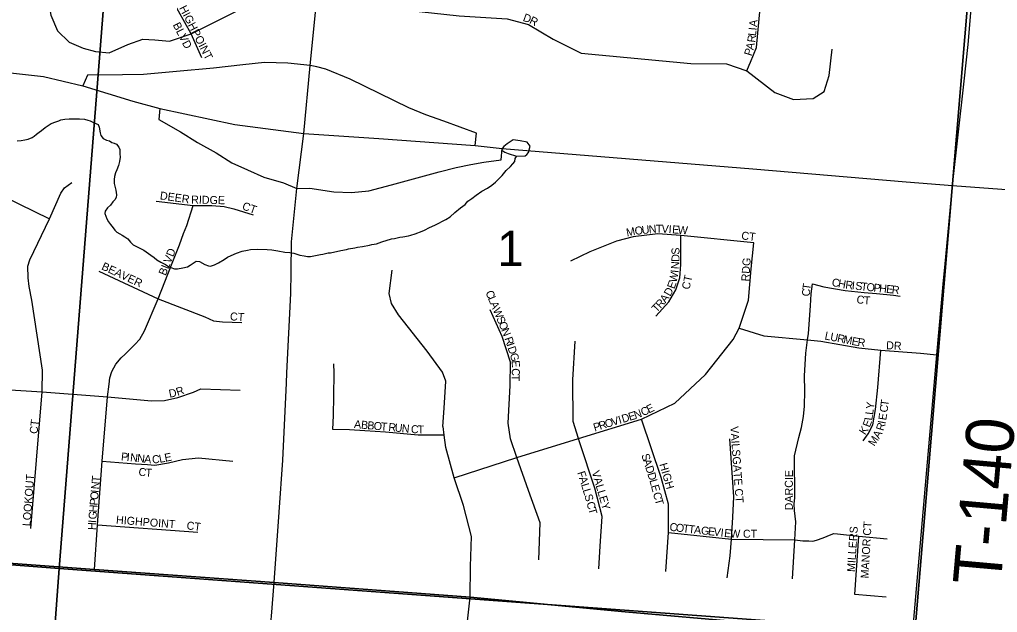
# Model space of a CAD drawing. Extents: x 1310247 to 1552180, y 377264 to 706493.
# Drawn here: x 1414286 to 1420398, y 506121 to 509829 of the extents above; entities that cross this region are included whole.
import ezdxf

# ---------------------------------------------------------------- set-up
doc = ezdxf.new("R2010")
doc.units = 0
for name, color, linetype in [('GM_X_County_Road', 7, 'Continuous'), ('GM_X_Interchange_Ramps', 7, 'Continuous'), ('GM_X_Minor_River', 7, 'Continuous'), ('GM_X_Section', 7, 'Continuous'), ('GM_X_Section_Text', 7, 'Continuous'), ('GM_X_State_Route', 7, 'Continuous'), ('GM_X_Township', 7, 'Continuous'), ('GM_X_Township_Road', 7, 'Continuous'), ('GM_X_Township_Road_Text', 7, 'Continuous'), ('GM_X_Township_Subdivision', 7, 'Continuous'), ('GM_X_Township_Subdivision_Text', 7, 'Continuous')]:
    doc.layers.add(name, color=color, linetype=linetype)

msp = doc.modelspace()

# ---------------------------------------------------------------- linework, layer by layer
at = {"layer": 'GM_X_County_Road'}
msp.add_lwpolyline([(1408861.5, 506921.2), (1408897.3, 506907.8), (1408977.9, 506871.8), (1409040.8, 506847.4), (1409093.1, 506831.5), (1409129.4, 506820.4), (1409220, 506815.1), (1409938.6, 506761), (1410365.3, 506728.9), (1410785.2, 506697.3), (1412080.1, 506594.4), (1412114.6, 506591.5), (1412570.9, 506553.7), (1413550.1, 506484), (1414754.7, 506390.5), (1415877.6, 506308.5)], dxfattribs=at)
at = {"layer": 'GM_X_Interchange_Ramps'}
for points in [[(1416101.7, 509542.3), (1415963.9, 509555.5), (1415817.9, 509560.2), (1415681.2, 509546.3), (1415498.2, 509525.4), (1415266.5, 509504.6), (1415060.3, 509486), (1414930.5, 509483.7), (1414710.4, 509481.4), (1414682.6, 509414.2)], [(1417134, 509041.2), (1417143.2, 509117.6), (1416937.3, 509194.5), (1416825.5, 509234.2), (1416719.1, 509277.5), (1416353, 509456.1), (1416201.1, 509518.8), (1416144.6, 509533.6), (1416101.7, 509542.3)], [(1415162.2, 509272.9), (1415157.6, 509203.3), (1415292, 509126.9), (1415398.6, 509059.7), (1415514.4, 508994.8), (1415614, 508932.3), (1415711.3, 508888.3), (1415813.3, 508844.2), (1415936.3, 508807.2), (1416019.8, 508772.6)], [(1416019.8, 508772.6), (1416100.6, 508774.7), (1416251.2, 508751.5), (1416360.1, 508746.9), (1416469, 508758.5), (1416610.3, 508795.6), (1416909.2, 508876.7), (1417015.8, 508904.5), (1417106.2, 508923), (1417187.3, 508936.9), (1417296.1, 508950.8), (1417303.1, 509022.6)]]:
    msp.add_lwpolyline(points, dxfattribs=at)
at = {"layer": 'GM_X_Minor_River'}
for points in [[(1414270.9, 509070.1), (1414297.2, 509073.2), (1414319.4, 509076.4), (1414339.7, 509081.6), (1414364.2, 509090.8), (1414378.6, 509100.3), (1414393.1, 509111.8), (1414409.7, 509125.3), (1414424.1, 509134.8), (1414447, 509154.1), (1414484.1, 509178.8), (1414512.6, 509189.8), (1414530.9, 509195.2), (1414545.3, 509202.7), (1414569.5, 509205.8), (1414595.8, 509208.9), (1414617.9, 509208), (1414646, 509209), (1414660.1, 509208.5), (1414692.2, 509205.3), (1414714.1, 509200.5), (1414728, 509195.9), (1414751.7, 509183), (1414777.4, 509172), (1414784.8, 509155.7), (1414789.6, 509121.3), (1414794.9, 509103), (1414808.3, 509084.4), (1414830.1, 509075.6), (1414848, 509070.9), (1414863.7, 509060.3), (1414877.6, 509055.8), (1414891.5, 509049.2), (1414906.9, 509030.6), (1414912.4, 509016.3), (1414913.4, 508990.1), (1414914.6, 508968), (1414911.6, 508941.9), (1414904.7, 508916.1), (1414893.6, 508888.3), (1414886.9, 508870.5), (1414880, 508846.6), (1414877.3, 508828.6), (1414878.4, 508804.5)], [(1417392.5, 508974.2), (1417446.4, 508975.9), (1417456.7, 508985.7), (1417467.1, 508997.4), (1417478.2, 509037.2), (1417458.8, 509061.8), (1417415, 509071), (1417371, 509076.2), (1417334.2, 509051.1), (1417313.7, 509035.6), (1417305.4, 509023.8), (1417301.1, 509011.9)], [(1417211.7, 508774.6), (1417238.6, 508793.7), (1417261.4, 508813), (1417278.1, 508828.5), (1417303.1, 508853.7), (1417328.4, 508884.9), (1417355.5, 508910), (1417370.2, 508927.6), (1417380.8, 508941.2), (1417383.4, 508959.2), (1417392, 508973), (1417392.5, 508974.2)], [(1417301.1, 509011.9), (1417318.8, 508999.4), (1417340.7, 508990.7), (1417392.5, 508974.2)], [(1414878.4, 508804.5), (1414883.5, 508778.2), (1414888.9, 508761.9), (1414891.9, 508733.6), (1414891.2, 508715.6), (1414882.7, 508701.8), (1414870.1, 508688.2), (1414855.3, 508668.7), (1414836.6, 508651.3), (1414821.8, 508631.7), (1414819.2, 508615.7), (1414824.6, 508599.4), (1414832, 508583.1), (1414841.4, 508564.7), (1414854.9, 508548.1), (1414872.2, 508527.3), (1414881.7, 508512.9), (1414895.3, 508500.3), (1414913, 508489.6), (1414926.8, 508481.1), (1414944.5, 508470.4), (1414962.1, 508457.7), (1414979.5, 508437), (1414996.9, 508420.2), (1415062.1, 508387.7), (1415091.5, 508366.5), (1415107.2, 508355.9), (1415128.7, 508341), (1415144.3, 508326.3), (1415169.8, 508311.3), (1415199.4, 508296.2), (1415217.2, 508285.5), (1415231, 508278.9), (1415254.8, 508270), (1415272.9, 508269.3), (1415307.3, 508276.1), (1415335.7, 508283.1), (1415352.1, 508292.5), (1415376.9, 508309.7), (1415391.2, 508317.2), (1415411.3, 508316.5), (1415444.8, 508297.2), (1415466.6, 508288.3), (1415480.6, 508287.8), (1415505, 508294.9), (1415529.6, 508308.1), (1415564.6, 508328.9), (1415585.2, 508342.2), (1415628.2, 508362.8), (1415642.5, 508368.2), (1415677.1, 508381), (1415711.5, 508387.8), (1415729.8, 508391.2), (1415772.1, 508393.6), (1415834.3, 508391.3), (1415862.4, 508388.3), (1415900.4, 508382.8), (1415944.3, 508375.2), (1415976.4, 508372), (1416000.3, 508367.1), (1416038.1, 508355.6), (1416066.1, 508350.6), (1416086.1, 508347.8), (1416104.1, 508347.2), (1416126.4, 508350.4), (1416166.9, 508358.9), (1416181.1, 508362.4), (1416215.5, 508369.2), (1416229.7, 508370.7), (1416294.5, 508384.4), (1416328.9, 508391.1), (1416343.2, 508394.6), (1416381.6, 508401.3), (1416397.8, 508404.7), (1416430.2, 508409.5), (1416472.7, 508418), (1416488.9, 508421.4), (1416517.2, 508426.4), (1416549.9, 508439.3), (1416610.9, 508457.1), (1416629.1, 508460.5), (1416663.5, 508467.2), (1416681.7, 508470.6), (1416716.2, 508477.3), (1416732.4, 508480.8), (1416758.9, 508489.8), (1416801.7, 508506.4), (1416818, 508511.8), (1416848.8, 508528.7), (1416863, 508534.2), (1416885.6, 508545.5), (1416951.2, 508579.2), (1416977.9, 508596.3), (1417007, 508621.4), (1417042.3, 508652.2), (1417071.3, 508673.3), (1417088.1, 508692.8), (1417112.8, 508709.9), (1417139.7, 508731), (1417174.8, 508755.9), (1417211.7, 508774.6)]]:
    msp.add_lwpolyline(points, dxfattribs=at)
at = {"layer": 'GM_X_Section'}
for points in [[(1409601, 512131.4), (1414953.7, 511702.6), (1414533.6, 506397), (1409190.5, 506806)], [(1414953.7, 511702.6), (1420324.2, 511263.3), (1419880.8, 505993.9), (1419763.1, 506010.4), (1414533.6, 506397)], [(1420324.2, 511263.3), (1425760.4, 510816.7), (1425255.7, 505582.2), (1425189.8, 505587.6), (1419880.8, 505993.9)], [(1414533.6, 506397), (1414234.1, 502333.5), (1408766.1, 501397.1), (1409190.5, 506806)], [(1414533.6, 506397), (1419763.1, 506010.4), (1419420.1, 501499.9), (1414234.1, 502333.5)]]:
    msp.add_lwpolyline(points, close=True, dxfattribs=at)
at = {"layer": 'GM_X_State_Route'}
for points in [[(1416062.4, 509116.6), (1416101.7, 509542.3), (1416150.8, 510021.2), (1416167.2, 510205.4), (1416209.5, 510524.7), (1416240.9, 510902.7), (1416262.2, 511124.8)], [(1409479.3, 509680.4), (1410613.6, 509563.2), (1412222.5, 509467.6), (1413312.6, 509542.6), (1413926.1, 509528.9), (1414437, 509472.1), (1414682.6, 509414.2), (1414995.4, 509319.2), (1415162.2, 509272.9), (1415632.6, 509173.2), (1416062.4, 509116.6)], [(1415983.5, 508249), (1415986.8, 508438.1), (1416019.8, 508772.6), (1416062.4, 509116.6)], [(1416062.4, 509116.6), (1416531.6, 509085.2), (1417134, 509041.2), (1417303.1, 509022.6), (1418869.5, 508895.8), (1419828.5, 508815.1), (1420118.1, 508790.7), (1420733.2, 508745.2), (1422884.3, 508567.5), (1423685.8, 508509.4), (1425275.2, 508364), (1425695.8, 508331.6), (1426930.7, 508228.9), (1427457.7, 508177.1), (1428081.4, 508068.2), (1430256.9, 507476.8), (1430387.7, 507439.7), (1430467.6, 507416.8)], [(1415957.3, 507619.2), (1415981.1, 508115), (1415983.5, 508249)], [(1415877.6, 506308.5), (1415908.7, 506747.4), (1415932.5, 507072.8), (1415954.2, 507554.1), (1415957.3, 507619.2)], [(1415805.5, 505579.3), (1415820.4, 505682.5), (1415843.7, 505931.8), (1415861.8, 506098.3), (1415877.6, 506308.5)]]:
    msp.add_lwpolyline(points, dxfattribs=at)
at = {"layer": 'GM_X_Township'}
for points in [[(1408158.9, 494897.9), (1408752, 502179.6), (1409220, 506815.1), (1409938.7, 506761), (1410365.3, 506728.9), (1410785.2, 506697.3), (1412080.1, 506594.4), (1412114.6, 506591.6), (1412570.8, 506553.8), (1413538.4, 506479.9), (1414754.7, 506390.5), (1415877.6, 506308.5), (1417102.2, 506217.1), (1418070.9, 506124.4), (1418831.7, 506057.7), (1419038.1, 506039.2), (1419868, 505981.9), (1420467.7, 505924.2), (1420708.1, 505905.7), (1421475, 505838), (1421803, 505818.4), (1422757.2, 505730.2), (1423386.7, 505686.1), (1424357.6, 505618.1)], [(1424357.6, 505618.1), (1423386.7, 505686.1), (1422757.2, 505730.2), (1421803, 505818.4), (1421475, 505838), (1420708.1, 505905.7), (1420467.7, 505924.2), (1419868, 505981.9), (1419038.1, 506039.2), (1418831.7, 506057.7), (1418070.9, 506124.4), (1417102.2, 506217.1), (1415877.6, 506308.5), (1414754.7, 506390.5), (1413538.4, 506479.9)]]:
    msp.add_lwpolyline(points, dxfattribs=at)
at = {"layer": 'GM_X_Township_Road'}
for points in [[(1420217.7, 509695), (1420287.5, 510555.8), (1420363.3, 511254.9)], [(1420190.5, 509443.8), (1420215.9, 509672.8), (1420217.7, 509695)], [(1420061.3, 508196.9), (1420068.9, 508279.2), (1420118.1, 508790.7), (1420190.5, 509443.8)], [(1419868, 505981.9), (1420018.5, 507732.7), (1420061.3, 508196.9)], [(1415877.6, 506308.5), (1416351.7, 506273.1)], [(1416351.7, 506273.1), (1417102.2, 506217.1), (1418070.9, 506124.4), (1418831.7, 506057.7), (1419038.1, 506039.2), (1419868, 505981.9), (1420467.7, 505924.2), (1420708.1, 505905.7), (1421474.9, 505838), (1421803, 505818.4), (1422757.3, 505730.2), (1423386.7, 505686.1), (1424352.3, 505618.5)]]:
    msp.add_lwpolyline(points, dxfattribs=at)
at = {"layer": 'GM_X_Township_Subdivision'}
for points in [[(1414609.7, 511348.1), (1414916.8, 511324.8), (1414885.7, 510959.2), (1414873.7, 510588.9), (1414849.8, 510250.3), (1414495.4, 510266.2), (1414479.5, 510027.2), (1414473.5, 509904), (1414481.3, 509856.3), (1414523.3, 509758.3), (1414597, 509688.6), (1414684.6, 509650.8), (1414760.2, 509628.8), (1414845.9, 509620.9), (1414963.3, 509672.7), (1415056.9, 509706.5), (1415132.6, 509702.4), (1415224.2, 509694.6), (1415359.6, 509740.4), (1415741.9, 509931.6), (1415843.5, 509991.3), (1415884.9, 510023.3), (1415974.9, 510037.2), (1416150.8, 510021.2)], [(1415425.8, 509589.3), (1415359.6, 509740.4), (1415240.1, 509953.5), (1415214.2, 510025.2), (1415206.3, 510057.1), (1415212.3, 510129.4), (1415218.2, 510262.2), (1415234.1, 510477.3), (1415285.9, 510981.2), (1415295.8, 511044.7), (1415296.6, 511102.5), (1415281.9, 511162.5)], [(1418832.3, 509507.3), (1418847, 509543.5), (1418854.5, 509563.4), (1418891.2, 509654.2), (1418937.7, 510147.7), (1418978.6, 510580.1)], [(1416150.8, 510021.2), (1416321.2, 510007.7), (1416430.1, 509983.5), (1416540.8, 509950.6), (1416628.1, 509915.2), (1416705.9, 509888.4), (1417034.4, 509852.1), (1417334.9, 509834), (1417466.3, 509798.2), (1417621.6, 509706.5), (1417796.8, 509618.9), (1418481.6, 509554.4), (1418704.8, 509551.2), (1418832.3, 509507.3), (1419007.5, 509371.9), (1419123, 509328.1), (1419246.4, 509336.1), (1419314.2, 509379.9), (1419346, 509479.5), (1419365.9, 509642.8)], [(1412693.2, 508523.3), (1413178.6, 508732), (1413368.4, 508813.4), (1413453.5, 508853), (1413558.8, 508900.8), (1413606.6, 508916.5), (1413647.7, 508923.9), (1413708.9, 508926.2), (1413811.2, 508905.2), (1414474.3, 508582.6)], [(1414357.7, 506645.7), (1414428.4, 507500.2), (1414430, 507636.4), (1414362.3, 508074.1), (1414346.6, 508160), (1414339.2, 508214.5), (1414339.1, 508287.1), (1414351.3, 508327.4), (1414474.3, 508582.6), (1414544.9, 508743.4), (1414567.2, 508776.4), (1414612.2, 508810.1)], [(1414754.7, 506390.5), (1414774.2, 506669.2), (1414801.7, 507066.5), (1414835.4, 507469.2), (1414845.9, 507549.2), (1414851.5, 507589.2), (1414862.7, 507628), (1414887.6, 507674.6), (1414921.6, 507713.2), (1414947.1, 507735.5), (1414982.5, 507771.5), (1415006.6, 507797.1), (1415038.5, 507830.3), (1415066.3, 507882.3), (1415153, 508082), (1415236, 508295.5), (1415285.9, 508421), (1415310.3, 508491.9), (1415332.2, 508541.2), (1415371.6, 508666.9)], [(1415140.7, 508692.6), (1415371.6, 508666.9), (1415489, 508666.7), (1415565.1, 508660.8), (1415625.1, 508645.6), (1415745.9, 508607.1)], [(1418875.7, 508431.9), (1418418.6, 508478.3), (1418276.2, 508488.3), (1418121.4, 508469.7), (1418017.3, 508443.7), (1417850.1, 508375.6), (1417730, 508317.4)], [(1417002.4, 506962.6), (1417393.6, 507089.9), (1417779.4, 507208.1), (1418174.2, 507330.3), (1418381.9, 507429.5), (1418572.8, 507610), (1418746.6, 507828.3), (1418784, 507900), (1418842.2, 508073.3), (1418858.2, 508270.5), (1418875.7, 508431.9)], [(1418262.8, 507973.7), (1418344.6, 508064), (1418388.7, 508138.5), (1418412.8, 508213), (1418420.2, 508298), (1418418.6, 508478.3)], [(1414782.5, 508255.3), (1415153, 508082), (1415444.8, 507969.6), (1415499.1, 507944.4), (1415554, 507937.7), (1415675.9, 507933.9)], [(1416932.9, 507284.1), (1416932.8, 507284.6), (1416939.1, 507397.9), (1416949.6, 507567.9), (1416929.9, 507623.8), (1416834.6, 507755.1), (1416655, 507981.7), (1416610.4, 508052.3), (1416596.8, 508115.5), (1416616, 508262.5)], [(1419116.2, 506330.8), (1419131.4, 506574.4), (1419138.6, 506688.4), (1419129.9, 506758.8), (1419128.2, 506800.7), (1419130.9, 506839), (1419129, 507100.2), (1419156.3, 507215.6), (1419173.1, 507278.6), (1419185.7, 507345.7), (1419192, 507410.8), (1419194.1, 507507.4), (1419192, 507601.8), (1419200.4, 507742.4), (1419211.8, 507826.1), (1419217.2, 507866.2), (1419229.8, 508038.3), (1419234, 508113.8), (1419242.4, 508176.8)], [(1419242.4, 508176.8), (1419313.8, 508157.9), (1419445.9, 508134.8), (1419565.5, 508122.3), (1419641.1, 508116), (1419748, 508105.5), (1419790, 508099.2)], [(1417532, 506450.1), (1417540.4, 506680.9), (1417467.1, 506883.3), (1417393.6, 507089.9), (1417353.8, 507207.8), (1417340, 507305.7), (1417352.3, 507541.4), (1417353.8, 507686.8), (1417301.8, 507847.5), (1417226.8, 508014.4)], [(1418784, 507900), (1418938.8, 507852), (1419211.8, 507826.1), (1419293.4, 507818.4), (1419532.5, 507776.5), (1419668.6, 507760.6), (1419916.5, 507742.9), (1420018.5, 507732.7)], [(1417906.4, 506394.3), (1417916, 506534.9), (1417927.6, 506721.3), (1417882.2, 506898.2), (1417785.6, 507188.5), (1417779.4, 507208.1), (1417745.7, 507315.6), (1417744.9, 507575.8), (1417759.6, 507817.2)], [(1419559, 507195), (1419590.5, 507239), (1419619.9, 507293.6), (1419636.7, 507390.1), (1419651.4, 507528.6), (1419668.6, 507760.6)], [(1416939.6, 507230.8), (1416938.6, 507230.8), (1416777.7, 507230.6), (1416574.2, 507249.5), (1416444.1, 507257.9), (1416347.6, 507264.2), (1416245, 507265.8), (1416248.7, 507352.5), (1416251.2, 507473.9), (1416252.4, 507620), (1416251.2, 507677)], [(1413571.9, 507534.1), (1413658.3, 507547.6), (1413733.5, 507548.6), (1414027.1, 507525.4), (1414428.4, 507500.2), (1414835.4, 507469.2), (1415110.7, 507443.9), (1415192.3, 507445.9), (1415275.9, 507465.8), (1415373.5, 507499.7), (1415419.3, 507519.6), (1415664.2, 507511.6)], [(1418324.5, 506378.4), (1418341.3, 506620.5), (1418342.5, 506797.6), (1418296.6, 506966), (1418174.2, 507330.3)], [(1417102.2, 506217.1), (1417102.2, 506217.1), (1417104.8, 506409.5), (1417111.1, 506596.2), (1417060.7, 506789.3), (1417002.4, 506962.6), (1416949.6, 507152.4), (1416939.6, 507230.8), (1416932.9, 507284.1)], [(1418708.4, 506336.9), (1418726.7, 506474.7), (1418735.9, 506578.7), (1418745.1, 506716.5), (1418749.7, 506845), (1418725.2, 507207.8)], [(1414801.7, 507066.5), (1415010.7, 507050.3), (1415087, 507046.8), (1415131.4, 507041.7), (1415216.6, 507056.9), (1415305.4, 507077.5), (1415404, 507087.6), (1415619.2, 507067.7)], [(1414774.2, 506669.2), (1415400.6, 506624.2)], [(1418341.3, 506620.5), (1418735.9, 506578.7), (1419131.4, 506574.4), (1419181.2, 506570.1), (1419219.4, 506568.3), (1419244.9, 506567.3), (1419266.5, 506574.2), (1419308.6, 506588.9), (1419358.6, 506609.5), (1419375.3, 506614.4), (1419398.9, 506613.4), (1419531.2, 506598.2), (1419708.6, 506582.7)], [(1419703, 506215.9), (1419505.7, 506233.1), (1419531.2, 506598.2)], [(1418167.1, 502818.4), (1418207, 503269.3), (1418248.8, 503665.6), (1418242.9, 503870.8), (1418219, 504111.8), (1418201.1, 504305), (1418151.4, 504444.3), (1418049.4, 504569.3), (1417895.2, 504737.9), (1417635.5, 505021.7), (1417520, 505148), (1417339.1, 505339.1), (1417173.6, 505513.9), (1417115.3, 505595.6), (1417062.1, 505737), (1417063.8, 505860.4), (1417102.2, 506217.1)]]:
    msp.add_lwpolyline(points, dxfattribs=at)

# ---------------------------------------------------------------- texts
at = {"layer": 'GM_X_Section_Text'}
msp.add_text('1', height=221, rotation=0.00001, dxfattribs=at).set_placement((1417271.9, 508286.8))
at = {"layer": 'GM_X_Township_Road_Text'}
msp.add_text('T-140', height=300, rotation=84.93291, dxfattribs=at).set_placement((1420417.4, 506282.5))
at = {"layer": 'GM_X_Township_Subdivision_Text'}
for s, rotation, p in [('HIGHPOINT', 297.23573, (1415282.6, 509901.4)), ('D', 339.74708, (1417428.5, 509822.3)), ('R', 332.82677, (1417468.3, 509807.7)), ('BLVD', 297.18004, (1415242.5, 509795.9)), ('I', 84.4268, (1418892.1, 509759.6)), ('A', 84.4268, (1418894.2, 509781.5)), ('R', 82.08052, (1418883, 509683.1)), ('L', 84.4268, (1418888.7, 509724.5)), ('P', 72.69541, (1418860.9, 509597.8)), ('A', 77.38797, (1418872.6, 509635.7)), ('DEER', 352.09102, (1415161.2, 508705)), ('RIDGE', 358.69618, (1415358.4, 508678.7)), ('CT', 340.55862, (1415673.5, 508643)), ('N', 5.86828, (1418221, 508492)), ('T', 0.16394, (1418263.4, 508496.5)), ('V', 356.3255, (1418297.7, 508496.6)), ('I', 356.10595, (1418341.6, 508493.8)), ('M', 11.27421, (1418083, 508471.5)), ('O', 7.21042, (1418133.9, 508481.7)), ('U', 6.38485, (1418177.4, 508487.2)), ('E', 356.10415, (1418363.5, 508492.3)), ('W', 356.09646, (1418398.7, 508489.9)), ('CT', 353.66314, (1418795.4, 508454.3)), ('BLVD', 68.19859, (1415199.6, 508224)), ('S', 89.99561, (1418410.9, 508358.4)), ('BEAVER', 334.79898, (1414794.4, 508268.6)), ('N', 85.94483, (1418407.4, 508266.7)), ('D', 89.66618, (1418410.7, 508314.1)), ('RDG', 86.18424, (1418846.5, 508190.1)), ('W', 78.43606, (1418392.7, 508181.7)), ('I', 83.9376, (1418404.9, 508242.9)), ('E', 70.11698, (1418378.5, 508140.9)), ('CT', 77.48124, (1418473, 508137.4)), ('T', 82.32772, (1419228, 508135)), ('C', 348.78293, (1419359.4, 508163.7)), ('H', 349.34695, (1419398.8, 508155.9)), ('R', 352.97318, (1419445.4, 508147.2)), ('I', 354.12621, (1419485.8, 508142.3)), ('S', 354.17305, (1419507.8, 508140)), ('T', 354.18536, (1419542.8, 508136.4)), ('O', 354.17632, (1419577.8, 508132.9)), ('P', 354.17116, (1419621.6, 508128.4)), ('C', 292.72823, (1417197, 508122.9)), ('D', 60.46913, (1418353, 508094.3)), ('C', 85.40476, (1419224.9, 508096.2)), ('H', 354.18043, (1419656.6, 508124.8)), ('E', 354.18536, (1419700.4, 508120.4)), ('R', 353.48951, (1419735.3, 508116.8)), ('L', 292.72935, (1417212.3, 508086.4)), ('A', 292.73083, (1417225.9, 508053.9)), ('T', 46.90303, (1418268.3, 507993.8)), ('R', 46.91083, (1418292.4, 508019.5)), ('A', 53.83937, (1418323.6, 508053.5)), ('C', 347.52783, (1419513.3, 508058.6)), ('T', 357.37208, (1419561.2, 508048.9)), ('CT', 356.63542, (1415600.5, 507948.3)), ('W', 292.73051, (1417242.9, 508013.4)), ('S', 292.73229, (1417265, 507960.6)), ('O', 292.7279, (1417278.6, 507928.1)), ('N', 291.9658, (1417295.6, 507887.7)), ('L', 348.7249, (1419315.4, 507829.3)), ('R', 288.57318, (1417316.3, 507835.2)), ('U', 348.7265, (1419349.9, 507822.4)), ('R', 348.71865, (1419393.1, 507813.8)), ('M', 348.72499, (1419431.9, 507806.1)), ('E', 348.78918, (1419483.7, 507795.8)), ('R', 352.40393, (1419521.6, 507788.3)), ('DR', 356.98329, (1419701.2, 507767.9)), ('I', 288.22762, (1417328.8, 507797.8)), ('D', 288.20686, (1417335.7, 507776.9)), ('G', 286.43025, (1417349.4, 507735.5)), ('E', 274.3348, (1417361.3, 507696)), ('C', 268.32423, (1417363.7, 507649.1)), ('T', 268.2647, (1417362.6, 507609.5)), ('D', 12.08789, (1415224.8, 507463.6)), ('R', 19.87641, (1415274.8, 507474.8)), ('T', 81.89262, (1419715.6, 507408.4)), ('N', 19.3926, (1418135.7, 507330.2)), ('C', 25.91769, (1418182.9, 507347.2)), ('E', 26.55864, (1418219.1, 507364.8)), ('L', 82.52203, (1419620.4, 507355)), ('Y', 82.50356, (1419624.9, 507389.9)), ('C', 81.89189, (1419710, 507369.1)), ('CT', 83.66313, (1414398.2, 507235.9)), ('A', 355.04304, (1416375.2, 507275.1)), ('R', 16.90167, (1417914.5, 507262.9)), ('O', 16.90327, (1417952.4, 507274.4)), ('V', 16.90024, (1417994.5, 507287.2)), ('I', 16.89059, (1418036.6, 507300)), ('D', 16.89614, (1418057.6, 507306.4)), ('E', 16.9034, (1418099.7, 507319.2)), ('E', 69.17166, (1419599.9, 507275.2)), ('L', 82.06945, (1419615.4, 507319.7)), ('E', 81.26877, (1419702.6, 507320.7)), ('B', 355.05536, (1416419, 507271.3)), ('B', 355.03973, (1416458.5, 507267.9)), ('O', 355.05434, (1416497.9, 507264.4)), ('T', 355.04919, (1416541.8, 507260.6)), ('R', 355.04356, (1416590, 507256.5)), ('U', 355.05434, (1416629.4, 507253)), ('N', 355.04304, (1416673.3, 507249.2)), ('C', 355.4316, (1416730.6, 507244.3)), ('T', 358.41145, (1416772.9, 507241)), ('P', 16.89683, (1417880.8, 507252.7)), ('VAILSGATE CT', 274.00423, (1418728.9, 507283.9)), ('K', 56.71911, (1419570.5, 507228)), ('R', 73.14484, (1419685.4, 507253.6)), ('I', 79.29642, (1419698.2, 507297.2)), ('M', 56.99445, (1419628.2, 507157.3)), ('A', 60.04366, (1419658.4, 507204.1)), ('P', 354.27989, (1414918.9, 507072.6)), ('I', 354.28245, (1414954, 507069.1)), ('N', 354.27527, (1414975.8, 507066.9)), ('N', 354.27527, (1415019.6, 507062.6)), ('A', 354.27527, (1415063.4, 507058.2)), ('C', 2.64166, (1415115.2, 507053.6)), ('L', 11.09736, (1415162.7, 507056.4)), ('E', 10.88398, (1415197.2, 507063.1)), ('S', 287.96844, (1418171.5, 507105.7)), ('C', 349.79507, (1415026.4, 506979.3)), ('T', 356.8535, (1415072, 506971.5)), ('A', 287.96494, (1418182.3, 507072.2)), ('D', 287.72303, (1418195.9, 507030.4)), ('HIGH', 286.38798, (1418284.3, 507048)), ('LOOKOUT', 85.73277, (1414354.1, 506659.2)), ('T', 85.03007, (1414786.5, 506933.6)), ('F', 287.81286, (1417771, 506995.8)), ('A', 287.62978, (1417781.8, 506962.4)), ('VALLEY', 286.22083, (1417861.7, 507000.2)), ('D', 287.01435, (1418209.2, 506988.6)), ('L', 286.17059, (1418222, 506946.7)), ('DARCIE', 90, (1419119.3, 506759.7)), ('N', 85.03214, (1414782.6, 506889.8)), ('L', 287.0957, (1417795.1, 506920.6)), ('L', 286.66785, (1417805.4, 506887)), ('E', 285.0071, (1418231.8, 506913.2)), ('P', 85.03728, (1414773.9, 506788.9)), ('O', 85.03214, (1414776.9, 506824)), ('I', 85.03687, (1414780.7, 506867.8)), ('S', 286.05423, (1417815.4, 506853.4)), ('C', 284.75778, (1418244.2, 506866.5)), ('T', 286.0148, (1418254.7, 506827)), ('H', 85.03214, (1414770.1, 506745.1)), ('C', 285.60016, (1417828.7, 506807)), ('T', 285.5307, (1417839.4, 506768.9)), ('G', 85.17463, (1414766.4, 506701.3)), ('HIGHPOINT', 355.48564, (1414887.9, 506676.7)), ('H', 88.16366, (1414763.3, 506636.1)), ('I', 85.64655, (1414764.7, 506679.5)), ('CT', 353.28755, (1415328.2, 506641.4)), ('C', 353.61153, (1418346.6, 506632.6)), ('O', 353.60429, (1418386, 506628.2)), ('T', 353.61831, (1418429.7, 506623.3)), ('T', 353.60701, (1418464.7, 506619.4)), ('A', 353.60456, (1418499.6, 506615.5)), ('G', 353.61577, (1418543.4, 506610.6)), ('E', 353.60701, (1418587.1, 506605.7)), ('V', 353.61577, (1418622.1, 506601.8)), ('MILLERS', 86.12175, (1419506.6, 506373.1)), ('MANOR CT', 86.86394, (1419592.4, 506333.1)), ('I', 353.60429, (1418665.8, 506596.9)), ('E', 353.82939, (1418687.9, 506594.4)), ('W', 358.35882, (1418727.2, 506590.3)), ('CT', 0.00001, (1418807.5, 506588.7))]:
    msp.add_text(s, height=50, rotation=rotation, dxfattribs=at).set_placement(p)

doc.saveas('drawing.dxf')
